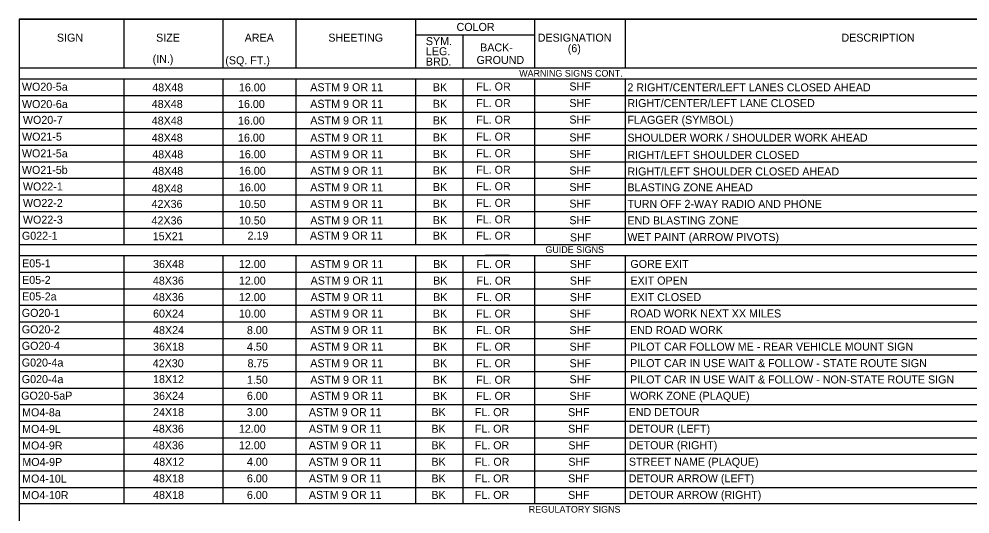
# Model space of a CAD drawing. Extents: x -439.1 to -407.9, y -458.1 to -437.7.
# Drawn here: x -439.11 to -421.29, y -446.95 to -437.68 of the extents above; entities that cross this region are included whole.
import ezdxf

# ---------------------------------------------------------------- set-up
doc = ezdxf.new("R2010")
doc.units = 0
for name, color, linetype in [('Common-Notes', 7, 'Continuous'), ('Draft_Named_Boundary', 7, 'Continuous'), ('Level 4', 7, 'Continuous'), ('Level 45', 7, 'Continuous')]:
    doc.layers.add(name, color=color, linetype=linetype)

msp = doc.modelspace()

# ---------------------------------------------------------------- linework, layer by layer
at = {"layer": 'Common-Notes'}
msp.add_line((-439.109, -445.834), (-418.049, -445.834), dxfattribs=at)
at = {"layer": 'Draft_Named_Boundary'}
msp.add_lwpolyline([(-439.109, -458.051), (-407.859, -458.051), (-407.859, -437.676), (-439.109, -437.676)], close=True, dxfattribs=at)
at = {"layer": 'Level 4'}
for p, q in [((-439.109, -437.676), (-418.049, -437.676)), ((-439.109, -437.676), (-439.109, -457.952)), ((-437.145, -437.676), (-437.145, -438.59)), ((-435.291, -437.676), (-435.291, -438.59)), ((-433.919, -437.676), (-433.919, -438.59)), ((-431.677, -437.676), (-431.677, -438.59)), ((-429.447, -437.676), (-429.447, -438.59)), ((-427.749, -437.676), (-427.749, -438.59)), ((-431.677, -437.972), (-429.447, -437.972)), ((-430.792, -437.972), (-430.792, -438.59)), ((-439.109, -438.59), (-418.049, -438.59)), ((-439.109, -438.8), (-418.049, -438.8)), ((-437.145, -438.8), (-437.145, -441.903)), ((-435.291, -438.8), (-435.291, -441.903)), ((-433.919, -438.8), (-433.919, -441.903)), ((-431.677, -438.8), (-431.677, -441.903)), ((-430.792, -438.8), (-430.792, -441.903)), ((-429.447, -438.8), (-429.447, -441.903)), ((-427.749, -438.8), (-427.749, -441.903)), ((-439.109, -439.11), (-418.049, -439.11)), ((-439.109, -439.421), (-418.049, -439.421)), ((-439.109, -439.731), (-418.049, -439.731)), ((-439.109, -440.041), (-418.049, -440.041)), ((-439.109, -440.351), (-418.049, -440.351)), ((-439.109, -440.662), (-418.049, -440.662)), ((-439.109, -440.972), (-418.049, -440.972)), ((-439.109, -441.282), (-418.049, -441.282)), ((-439.109, -441.593), (-418.049, -441.593)), ((-439.109, -441.903), (-418.049, -441.903)), ((-439.109, -442.11), (-418.049, -442.11)), ((-437.145, -442.11), (-437.145, -446.765)), ((-435.291, -442.11), (-435.291, -446.455)), ((-433.919, -442.11), (-433.919, -446.765)), ((-431.677, -442.11), (-431.677, -446.455)), ((-430.792, -442.11), (-430.792, -446.455)), ((-429.916, -442.11), (-430.371, -442.11)), ((-429.447, -442.11), (-429.447, -446.765)), ((-427.749, -442.11), (-427.749, -446.765)), ((-439.109, -442.421), (-418.049, -442.421)), ((-439.109, -442.421), (-439.109, -442.731)), ((-439.109, -442.731), (-418.049, -442.731)), ((-439.109, -443.041), (-418.049, -443.041)), ((-439.109, -443.352), (-418.049, -443.352)), ((-439.109, -443.662), (-418.049, -443.662)), ((-439.109, -443.972), (-418.049, -443.972)), ((-439.109, -444.283), (-418.049, -444.283)), ((-439.109, -444.593), (-418.049, -444.593)), ((-439.109, -444.903), (-418.049, -444.903)), ((-439.109, -445.214), (-418.049, -445.214)), ((-439.109, -445.524), (-418.049, -445.524)), ((-439.109, -446.145), (-418.049, -446.145)), ((-439.109, -446.455), (-418.049, -446.455)), ((-435.291, -446.455), (-435.291, -446.765)), ((-431.677, -446.455), (-431.677, -446.765)), ((-430.792, -446.455), (-430.792, -446.765)), ((-418.049, -446.765), (-439.109, -446.765))]:
    msp.add_line(p, q, dxfattribs=at)

# ---------------------------------------------------------------- texts
for s, height, p in [('COLOR', 0.15, (-430.909, -437.899)), ('SIGN', 0.15, (-438.399, -438.1)), ('SIZE', 0.15, (-436.54, -438.1)), ('AREA', 0.15, (-434.88, -438.1)), ('SHEETING', 0.15, (-433.312, -438.1)), ('SYM.', 0.15, (-431.484, -438.165)), ('DESIGNATION', 0.15, (-429.388, -438.1)), ('DESCRIPTION', 0.15, (-423.696, -438.1)), ('LEG.', 0.15, (-431.484, -438.355)), ('BACK-', 0.15, (-430.467, -438.284)), ('(6)', 0.15, (-428.825, -438.299)), ('BRD.', 0.15, (-431.484, -438.549)), ('GROUND', 0.15, (-430.534, -438.518)), ('WARNING SIGNS CONT.', 0.125, (-429.735, -438.756)), ('WO20-5a', 0.15, (-439.055, -439.02)), ('ASTM 9 OR 11', 0.15044, (-433.651, -439.03)), ('BK', 0.15, (-431.353, -439.03)), ('FL. OR', 0.15, (-430.541, -439.016)), ('SHF', 0.15, (-428.795, -439.015)), ('2 RIGHT/CENTER/LEFT LANES CLOSED AHEAD', 0.15, (-427.707, -439.032)), ('WO20-6a', 0.15, (-439.054, -439.345)), ('ASTM 9 OR 11', 0.15044, (-433.651, -439.341)), ('BK', 0.15, (-431.353, -439.34)), ('FL. OR', 0.15, (-430.541, -439.326)), ('SHF', 0.15, (-428.795, -439.325)), ('RIGHT/CENTER/LEFT LANE CLOSED ', 0.15, (-427.707, -439.327)), ('WO20-7', 0.15, (-439.036, -439.641)), ('FL. OR', 0.15, (-430.541, -439.637)), ('SHF', 0.15, (-428.795, -439.635)), ('FLAGGER (SYMBOL)', 0.15, (-427.707, -439.64)), ('ASTM 9 OR 11', 0.15044, (-433.651, -439.651)), ('BK', 0.15, (-431.353, -439.651)), ('WO21-5', 0.15, (-439.053, -439.956)), ('ASTM 9 OR 11', 0.15044, (-433.651, -439.976)), ('BK', 0.15, (-431.353, -439.97)), ('FL. OR', 0.15, (-430.541, -439.955)), ('SHF', 0.15, (-428.795, -439.97)), ('SHOULDER WORK / SHOULDER WORK AHEAD', 0.15, (-427.707, -439.975)), ('WO21-5a', 0.15, (-439.055, -440.269)), ('ASTM 9 OR 11', 0.15044, (-433.651, -440.286)), ('BK', 0.15, (-431.353, -440.28)), ('FL. OR', 0.15, (-430.541, -440.266)), ('SHF', 0.15, (-428.795, -440.28)), ('RIGHT/LEFT SHOULDER CLOSED', 0.15, (-427.707, -440.298)), ('WO21-5b', 0.15, (-439.055, -440.579)), ('ASTM 9 OR 11', 0.15044, (-433.651, -440.596)), ('BK', 0.15, (-431.353, -440.59)), ('FL. OR', 0.15, (-430.541, -440.576)), ('SHF', 0.15, (-428.795, -440.59)), ('RIGHT/LEFT SHOULDER CLOSED AHEAD', 0.15, (-427.707, -440.608)), ('WO22-1', 0.15, (-439.036, -440.89)), ('FL. OR', 0.15, (-430.541, -440.886)), ('ASTM 9 OR 11', 0.15044, (-433.651, -440.907)), ('BK', 0.15, (-431.353, -440.9)), ('SHF', 0.15, (-428.795, -440.901)), ('BLASTING ZONE AHEAD', 0.15, (-427.707, -440.906)), ('WO22-2', 0.15, (-439.036, -441.2)), ('ASTM 9 OR 11', 0.15044, (-433.651, -441.217)), ('BK', 0.15, (-431.353, -441.211)), ('FL. OR', 0.15, (-430.541, -441.197)), ('SHF', 0.15, (-428.795, -441.211)), ('TURN OFF 2-WAY RADIO AND PHONE', 0.15, (-427.707, -441.216)), ('WO22-3', 0.15, (-439.036, -441.511)), ('ASTM 9 OR 11', 0.15044, (-433.651, -441.527)), ('BK', 0.15, (-431.353, -441.521)), ('FL. OR', 0.15, (-430.541, -441.507)), ('SHF', 0.15, (-428.795, -441.521)), ('END BLASTING ZONE', 0.15, (-427.707, -441.527)), ('G022-1', 0.15, (-439.055, -441.813)), ('ASTM 9 OR 11', 0.15044, (-433.657, -441.81)), ('BK', 0.15, (-431.352, -441.811)), ('FL. OR', 0.15, (-430.541, -441.811)), ('SHF', 0.15, (-428.785, -441.844)), ('WET PAINT (ARROW PIVOTS)', 0.15, (-427.707, -441.837)), ('GUIDE SIGNS', 0.125, (-429.243, -442.061)), ('E05-1', 0.15, (-439.051, -442.33)), ('ASTM 9 OR 11', 0.15044, (-433.645, -442.344)), ('BK', 0.15, (-431.348, -442.343)), ('FL. OR', 0.15, (-430.536, -442.343)), ('SHF', 0.15, (-428.786, -442.343)), ('GORE EXIT', 0.15, (-427.651, -442.342)), ('E05-2', 0.15, (-439.051, -442.641)), ('ASTM 9 OR 11', 0.15044, (-433.645, -442.654)), ('BK', 0.15, (-431.348, -442.654)), ('FL. OR', 0.15, (-430.536, -442.654)), ('SHF', 0.15, (-428.786, -442.654)), ('EXIT OPEN', 0.15, (-427.651, -442.653)), ('E05-2a', 0.15, (-439.051, -442.951)), ('ASTM 9 OR 11', 0.15044, (-433.645, -442.964)), ('BK', 0.15, (-431.348, -442.964)), ('FL. OR', 0.15, (-430.536, -442.964)), ('SHF', 0.15, (-428.786, -442.964)), ('EXIT CLOSED', 0.15, (-427.651, -442.963)), ('GO20-1', 0.15, (-439.057, -443.259)), ('ASTM 9 OR 11', 0.15044, (-433.651, -443.272)), ('BK', 0.15, (-431.353, -443.272)), ('FL. OR', 0.15, (-430.542, -443.272)), ('SHF', 0.15, (-428.792, -443.272)), ('ROAD WORK NEXT XX MILES', 0.15, (-427.657, -443.27)), ('GO20-2', 0.15, (-439.057, -443.568)), ('ASTM 9 OR 11', 0.15044, (-433.651, -443.582)), ('BK', 0.15, (-431.353, -443.582)), ('FL. OR', 0.15, (-430.542, -443.582)), ('SHF', 0.15, (-428.792, -443.582)), ('END ROAD WORK', 0.15, (-427.657, -443.581)), ('GO20-4', 0.15, (-439.057, -443.876)), ('ASTM 9 OR 11', 0.15044, (-433.651, -443.892)), ('BK', 0.15, (-431.353, -443.892)), ('FL. OR', 0.15, (-430.542, -443.892)), ('SHF', 0.15, (-428.792, -443.892)), ('PILOT CAR FOLLOW ME - REAR VEHICLE MOUNT SIGN', 0.15, (-427.657, -443.891)), ('G020-4a', 0.15, (-439.057, -444.19)), ('ASTM 9 OR 11', 0.15044, (-433.651, -444.203)), ('BK', 0.15, (-431.353, -444.203)), ('FL. OR', 0.15, (-430.542, -444.203)), ('SHF', 0.15, (-428.792, -444.203)), ('PILOT CAR IN USE WAIT & FOLLOW - STATE ROUTE SIGN', 0.15, (-427.657, -444.201)), ('G020-4a', 0.15, (-439.057, -444.501)), ('ASTM 9 OR 11', 0.15044, (-433.651, -444.513)), ('BK', 0.15, (-431.353, -444.513)), ('FL. OR', 0.15, (-430.542, -444.513)), ('SHF', 0.15, (-428.792, -444.503)), ('PILOT CAR IN USE WAIT & FOLLOW - NON-STATE ROUTE SIGN', 0.15, (-427.657, -444.507)), ('GO20-5aP', 0.15, (-439.068, -444.81)), ('ASTM 9 OR 11', 0.15044, (-433.651, -444.814)), ('FL. OR', 0.15, (-430.542, -444.814)), ('SHF', 0.15, (-428.792, -444.814)), ('WORK ZONE (PLAQUE)', 0.15, (-427.657, -444.813)), ('BK', 0.15, (-431.353, -444.814)), ('MO4-8a', 0.15, (-439.051, -445.123)), ('ASTM 9 OR 11', 0.15044, (-433.677, -445.12)), ('BK', 0.15, (-431.38, -445.119)), ('FL. OR', 0.15, (-430.568, -445.119)), ('SHF', 0.15, (-428.818, -445.119)), ('END DETOUR', 0.15, (-427.683, -445.118)), ('MO4-9L', 0.15, (-439.051, -445.434)), ('ASTM 9 OR 11', 0.15044, (-433.677, -445.43)), ('BK', 0.15, (-431.38, -445.43)), ('FL. OR', 0.15, (-430.568, -445.43)), ('SHF', 0.15, (-428.818, -445.43)), ('DETOUR (LEFT)', 0.15, (-427.683, -445.429)), ('MO4-9R', 0.15, (-439.051, -445.744)), ('ASTM 9 OR 11', 0.15044, (-433.677, -445.74)), ('BK', 0.15, (-431.38, -445.74)), ('FL. OR', 0.15, (-430.568, -445.74)), ('SHF', 0.15, (-428.814, -445.74)), ('DETOUR (RIGHT)', 0.15, (-427.683, -445.739)), ('MO4-9P', 0.15, (-439.047, -446.054)), ('ASTM 9 OR 11', 0.15044, (-433.677, -446.051)), ('BK', 0.15, (-431.38, -446.05)), ('FL. OR', 0.15, (-430.565, -446.05)), ('SHF', 0.15, (-428.814, -446.05)), ('STREET NAME (PLAQUE)', 0.15, (-427.679, -446.049)), ('MO4-10L', 0.15, (-439.051, -446.365)), ('ASTM 9 OR 11', 0.15044, (-433.677, -446.361)), ('BK', 0.15, (-431.38, -446.361)), ('FL. OR', 0.15, (-430.568, -446.361)), ('SHF', 0.15, (-428.818, -446.361)), ('DETOUR ARROW (LEFT)', 0.15, (-427.683, -446.36)), ('MO4-10R', 0.15, (-439.051, -446.675)), ('ASTM 9 OR 11', 0.15044, (-433.677, -446.671)), ('BK', 0.15, (-431.38, -446.671)), ('FL. OR', 0.15, (-430.568, -446.671)), ('SHF', 0.15, (-428.818, -446.671)), ('DETOUR ARROW (RIGHT)', 0.15, (-427.683, -446.67)), ('REGULATORY SIGNS', 0.125, (-429.556, -446.928))]:
    msp.add_text(s, height=height, dxfattribs=at).set_placement(p)
at = {"layer": 'Level 45'}
for s, p in [('(IN.)', (-436.605, -438.498)), ('(SQ. FT.)', (-435.243, -438.525)), ('48X48', (-436.612, -439.034)), ('16.00', (-434.988, -439.033)), ('48X48', (-436.621, -439.343)), ('16.00', (-435.005, -439.343)), ('48X48', (-436.621, -439.654)), ('16.00', (-435.005, -439.654)), ('48X48', (-436.621, -439.975)), ('16.00', (-435.005, -439.975)), ('48X48', (-436.612, -440.287)), ('16.00', (-434.988, -440.285)), ('48X48', (-436.612, -440.597)), ('16.00', (-434.988, -440.596)), ('48X48', (-436.621, -440.927)), ('16.00', (-434.988, -440.906)), ('42X36', (-436.625, -441.217)), ('10.50', (-434.988, -441.217)), ('42X36', (-436.625, -441.527)), ('10.50', (-434.988, -441.527)), ('15X21', (-436.603, -441.823)), ('2.19', (-434.826, -441.811)), ('36X48', (-436.597, -442.343)), ('12.00', (-434.988, -442.343)), ('48X36', (-436.6, -442.654)), ('12.00', (-434.988, -442.654)), ('48X36', (-436.6, -442.964)), ('12.00', (-434.988, -442.964)), ('60X24', (-436.597, -443.272)), ('10.00', (-434.988, -443.272)), ('48X24', (-436.597, -443.582)), ('8.00', (-434.838, -443.582)), ('36X18', (-436.597, -443.892)), ('4.50', (-434.838, -443.892)), ('42X30', (-436.603, -444.203)), ('8.75', (-434.826, -444.203)), ('18X12', (-436.597, -444.5)), ('1.50', (-434.838, -444.513)), ('36X24', (-436.597, -444.814)), ('6.00', (-434.838, -444.814)), ('24X18', (-436.597, -445.119)), ('3.00', (-434.838, -445.119)), ('48X36', (-436.6, -445.43)), ('12.00', (-434.988, -445.43)), ('48X36', (-436.6, -445.74)), ('12.00', (-434.988, -445.74)), ('48X12', (-436.593, -446.05)), ('4.00', (-434.838, -446.05)), ('48X18', (-436.597, -446.361)), ('6.00', (-434.838, -446.361)), ('48X18', (-436.597, -446.671)), ('6.00', (-434.838, -446.671))]:
    msp.add_text(s, height=0.15, dxfattribs=at).set_placement(p)

doc.saveas('drawing.dxf')
